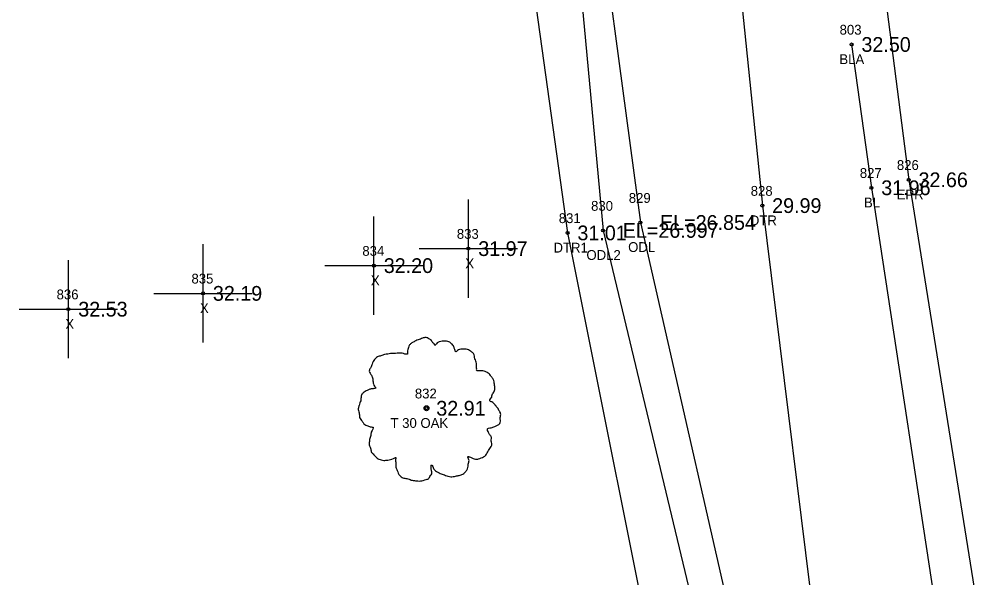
# Model space of a CAD drawing. Extents: x 2042211 to 2045853, y 303080 to 309569.
# Drawn here: x 2042754.4 to 2042852.8, y 307040.8 to 307097.7 of the extents above; entities that cross this region are included whole.
import ezdxf

# ---------------------------------------------------------------- set-up
doc = ezdxf.new("R2010")
doc.units = 0
for name, color, linetype in [('BR_500YR_SCOUR', 7, 'Continuous'), ('RD_DTM_BkLn1', 7, 'Continuous'), ('RD_DTM_BkLn_txCode', 7, 'Continuous'), ('RD_EX_H2O', 7, 'Continuous'), ('RD_EX_H2O_txCode', 7, 'Continuous'), ('RD_EX_Misc', 7, 'Continuous'), ('RD_EX_Misc_txCode', 7, 'Continuous'), ('RD_EX_Road', 7, 'Continuous'), ('RD_EX_Road_txCode', 7, 'Continuous'), ('RD_EX_TX_H2O_ELEV', 7, 'Continuous'), ('RD_EX_TX_Misc_ELEV', 7, 'Continuous'), ('RD_EX_TX_Road_ELEV', 7, 'Continuous'), ('RD_EX_TX_VEG_ELEV', 7, 'Continuous'), ('RD_EX_VEG_txCode', 7, 'Continuous'), ('RD_SMD_Locator', 7, 'Continuous')]:
    doc.layers.add(name, color=color, linetype=linetype)

msp = doc.modelspace()

# ---------------------------------------------------------------- linework, layer by layer
at = {"layer": 'BR_500YR_SCOUR'}
for centre, radius in [((2042795.884, 307058.081), 0.25), ((2042795.884, 307058.081), 0.15), ((2042795.871, 307058.062), 0.0001)]:
    msp.add_circle(centre, radius, dxfattribs=at)
for points in [[(2042796.016, 307065.248), (2042795.716, 307065.273), (2042795.391, 307065.173), (2042795.141, 307065.073), (2042794.916, 307064.998), (2042794.692, 307064.898), (2042794.392, 307064.723), (2042794.167, 307064.523), (2042794.042, 307064.273), (2042793.992, 307064.048), (2042793.942, 307063.774), (2042793.942, 307063.599), (2042793.817, 307063.574), (2042793.667, 307063.599), (2042793.417, 307063.674), (2042793.167, 307063.674), (2042792.917, 307063.674), (2042792.567, 307063.649), (2042792.218, 307063.649), (2042791.943, 307063.599), (2042791.618, 307063.549), (2042791.243, 307063.424), (2042790.893, 307063.299), (2042790.593, 307063.049), (2042790.343, 307062.574), (2042790.218, 307062.224), (2042790.069, 307061.974), (2042790.218, 307061.525), (2042790.393, 307061.175), (2042790.418, 307060.975), (2042790.493, 307060.55), (2042790.593, 307060.325), (2042790.718, 307060.125), (2042790.643, 307060.1), (2042790.268, 307060.05), (2042789.969, 307059.95), (2042789.544, 307059.725), (2042789.319, 307059.5), (2042789.219, 307059.175), (2042789.194, 307058.826), (2042789.094, 307058.626), (2042789.019, 307058.351), (2042788.994, 307058.276), (2042788.944, 307057.951), (2042789.044, 307057.501), (2042789.069, 307057.151), (2042789.194, 307056.926), (2042789.344, 307056.752), (2042789.519, 307056.502), (2042789.919, 307056.277), (2042790.243, 307056.177), (2042790.443, 307056.152), (2042790.268, 307055.652), (2042790.218, 307055.302), (2042790.094, 307054.902), (2042790.094, 307054.827), (2042790.044, 307054.353), (2042790.193, 307054.028), (2042790.268, 307053.653), (2042790.443, 307053.428), (2042790.718, 307053.128), (2042791.043, 307052.903), (2042791.543, 307052.778), (2042791.943, 307052.803), (2042792.518, 307052.978), (2042792.767, 307053.053), (2042792.742, 307052.878), (2042792.767, 307052.503), (2042792.767, 307052.079), (2042792.917, 307051.754), (2042793.017, 307051.479), (2042793.167, 307051.229), (2042793.492, 307051.004), (2042793.892, 307050.929), (2042794.317, 307050.779), (2042794.767, 307050.704), (2042795.266, 307050.679), (2042795.866, 307050.829), (2042796.141, 307050.954), (2042796.241, 307051.129), (2042796.441, 307051.504), (2042796.391, 307051.729), (2042796.416, 307052.329), (2042796.516, 307052.154), (2042796.691, 307051.804), (2042797.19, 307051.504), (2042797.59, 307051.329), (2042798.065, 307051.179), (2042798.365, 307051.104), (2042798.84, 307051.179), (2042799.215, 307051.254), (2042799.589, 307051.379), (2042799.889, 307051.654), (2042800.064, 307051.929), (2042800.114, 307052.204), (2042800.189, 307052.578), (2042800.239, 307052.753)], [(2042800.239, 307052.753), (2042800.164, 307052.928), (2042800.114, 307053.178), (2042800.189, 307053.153), (2042800.364, 307053.103), (2042800.639, 307052.978), (2042800.864, 307052.903), (2042801.189, 307052.928), (2042801.464, 307053.028), (2042801.913, 307053.303), (2042802.188, 307053.778), (2042802.463, 307054.178), (2042802.538, 307054.503), (2042802.488, 307054.727), (2042802.463, 307055.227), (2042802.263, 307055.477), (2042802.213, 307055.602), (2042802.113, 307056.002), (2042802.188, 307056.052), (2042802.463, 307056.102), (2042802.838, 307056.227), (2042803.113, 307056.352), (2042803.338, 307056.527), (2042803.413, 307056.752), (2042803.388, 307057.151), (2042803.438, 307057.551), (2042803.363, 307057.701), (2042803.263, 307057.851), (2042803.188, 307058.051), (2042803.038, 307058.201), (2042802.938, 307058.351), (2042802.838, 307058.451), (2042802.713, 307058.601), (2042802.538, 307058.726), (2042802.388, 307058.776), (2042802.338, 307058.926), (2042802.488, 307059.126), (2042802.538, 307059.225), (2042802.563, 307059.45), (2042802.788, 307059.8), (2042802.838, 307060.2), (2042802.788, 307060.625), (2042802.738, 307060.9), (2042802.588, 307061.175), (2042802.388, 307061.425), (2042802.263, 307061.599), (2042802.088, 307061.724), (2042801.763, 307061.849), (2042801.514, 307061.899), (2042801.164, 307061.899), (2042800.964, 307061.949), (2042800.989, 307061.999), (2042800.989, 307062.149), (2042800.989, 307062.424), (2042800.914, 307062.874), (2042800.764, 307063.374), (2042800.764, 307063.399), (2042800.664, 307063.649), (2042800.439, 307063.848), (2042800.264, 307063.948), (2042800.064, 307064.073), (2042799.814, 307064.098), (2042799.514, 307064.098), (2042799.24, 307064.048), (2042799.04, 307063.948), (2042798.865, 307063.823), (2042798.79, 307063.973), (2042798.69, 307064.273), (2042798.64, 307064.423), (2042798.49, 307064.598), (2042798.265, 307064.798), (2042797.815, 307064.923), (2042797.19, 307064.848), (2042796.891, 307064.648), (2042796.741, 307064.473), (2042796.691, 307064.598), (2042796.491, 307064.798), (2042796.391, 307064.973), (2042796.216, 307065.098), (2042796.066, 307065.198), (2042795.966, 307065.248)]]:
    msp.add_spline(points, degree=3, dxfattribs=at)
at = {"layer": 'RD_DTM_BkLn1'}
msp.add_lwpolyline([(2042839.169, 307095.106), (2042841.186, 307080.523), (2042848.71, 307031.328), (2042857.636, 306982.339), (2042868.252, 306933.785), (2042879.621, 306884.9), (2042891.371, 306836.606), (2042906.047, 306788.555), (2042920.383, 306740.357), (2042936.302, 306692.681), (2042942.201, 306670.77), (2042952.719, 306646.491), (2042972.882, 306600.437), (2042993.942, 306554.963), (2043015.194, 306509.481), (2043037.058, 306464.501), (2043060.221, 306420.453)], dxfattribs=at)
at = {"layer": 'RD_EX_H2O'}
for points in [[(2042809.741, 307126.164), (2042806.558, 307122.634), (2042790.31, 307116.781), (2042788.489, 307114.776), (2042791.888, 307113.566), (2042804.809, 307114.936), (2042810.254, 307075.927), (2042820.25, 307025.916), (2042830.402, 306977.214), (2042843.286, 306928.12), (2042852.907, 306878.242), (2042864.554, 306828.434), (2042879.232, 306781.717), (2042889.452, 306748.733), (2042886.162, 306741.984), (2042888.342, 306727.944), (2042896.131, 306676.354), (2042885.674, 306665.433), (2042857.251, 306612.72)], [(2042809.741, 307126.164), (2042815.006, 307124.307), (2042821.793, 307118.991), (2042825.803, 307110.204), (2042827.879, 307100.209), (2042830.079, 307078.706), (2042836.245, 307029.115), (2042845.477, 306980.043), (2042852.07, 306929.459), (2042864.584, 306881.255), (2042879.311, 306833.064), (2042893.367, 306784.782), (2042908.764, 306736.234), (2042928.775, 306689.39), (2042938.935, 306669.11)], [(2042812.202, 307117.747), (2042817.664, 307076.987), (2042828.965, 307027.386), (2042840.42, 306978.95), (2042848.435, 306929.659), (2042859.837, 306880.358), (2042873.681, 306831.671), (2042888.543, 306783.43), (2042900.594, 306749.272), (2042902.903, 306733.666), (2042926.042, 306688.214), (2042936.455, 306668.372), (2042947.444, 306643.989), (2042966.182, 306597.912), (2042985.34, 306551.144), (2042987.611, 306538.586)], [(2042810.023, 307117.36), (2042813.866, 307076.179), (2042825.646, 307027.003), (2042835.988, 306978.447), (2042846.189, 306929.265), (2042857.498, 306879.973), (2042870.301, 306830.673), (2042885.373, 306782.676), (2042895.573, 306748.275), (2042892.025, 306740.631), (2042891.661, 306731.268), (2042905.953, 306680.583), (2042906.869, 306643.176), (2042864.966, 306605.633)]]:
    msp.add_lwpolyline(points, dxfattribs=at)
at = {"layer": 'RD_EX_Misc'}
for p, q in [((2042800.156, 307069.328), (2042800.156, 307079.328)), ((2042790.538, 307067.597), (2042790.538, 307077.597)), ((2042773.139, 307064.774), (2042773.139, 307074.774)), ((2042795.156, 307074.328), (2042805.156, 307074.328)), ((2042759.432, 307063.165), (2042759.432, 307073.165)), ((2042785.538, 307072.597), (2042795.538, 307072.597)), ((2042768.139, 307069.774), (2042778.139, 307069.774)), ((2042754.432, 307068.165), (2042764.432, 307068.165))]:
    msp.add_line(p, q, dxfattribs=at)
at = {"layer": 'RD_EX_Road'}
msp.add_lwpolyline([(2042826.878, 307329.287), (2042828.013, 307279.816), (2042830.497, 307230.241), (2042834.094, 307180.367), (2042835.887, 307157.733), (2042833.55, 307154.384), (2042836.54, 307132.831), (2042837.327, 307130.114), (2042837.641, 307128.77), (2042839.219, 307126.163), (2042844.982, 307081.334), (2042852.857, 307032.13), (2042861.739, 306982.988), (2042871.664, 306934.616), (2042883.382, 306885.882), (2042895.938, 306837.564), (2042909.761, 306789.886)], dxfattribs=at)
at = {"layer": 'RD_SMD_Locator'}
for centre in [(2042839.169, 307095.106), (2042844.982, 307081.334), (2042841.186, 307080.523), (2042830.079, 307078.706), (2042817.664, 307076.987), (2042813.866, 307076.179), (2042810.254, 307075.927), (2042800.156, 307074.328), (2042790.538, 307072.597), (2042773.139, 307069.774), (2042759.432, 307068.165)]:
    msp.add_circle(centre, 0.15, dxfattribs=at)

# ---------------------------------------------------------------- texts
at = {"layer": 'RD_DTM_BkLn_txCode'}
for s, p in [('803', (2042837.948, 307096.106)), ('BLA', (2042837.925, 307093.106)), ('827', (2042840.005, 307081.523)), ('BL', (2042840.43, 307078.523))]:
    msp.add_text(s, height=1, dxfattribs=at).set_placement(p)
at = {"layer": 'RD_EX_H2O_txCode'}
for s, p in [('828', (2042828.897, 307079.706)), ('830', (2042812.645, 307078.179)), ('829', (2042816.483, 307078.987)), ('831', (2042809.357, 307076.927)), ('DTR', (2042828.811, 307076.706)), ('DTR1', (2042808.821, 307073.927)), ('ODL2', (2042812.173, 307073.179)), ('ODL', (2042816.42, 307073.987))]:
    msp.add_text(s, height=1, dxfattribs=at).set_placement(p)
at = {"layer": 'RD_EX_Misc_txCode'}
for s, p in [('833', (2042798.975, 307075.328)), ('834', (2042789.357, 307073.597)), ('X', (2042799.841, 307072.328)), ('835', (2042771.958, 307070.774)), ('X', (2042790.223, 307070.597)), ('836', (2042758.228, 307069.165)), ('X', (2042772.824, 307067.774)), ('X', (2042759.117, 307066.165))]:
    msp.add_text(s, height=1, dxfattribs=at).set_placement(p)
at = {"layer": 'RD_EX_Road_txCode'}
for s, p in [('826', (2042843.778, 307082.334)), ('EPR', (2042843.754, 307079.334))]:
    msp.add_text(s, height=1, dxfattribs=at).set_placement(p)
at = {"layer": 'RD_EX_TX_H2O_ELEV'}
for s, p in [('29.99', (2042831.079, 307077.956)), ('EL=26.854', (2042819.664, 307076.237)), ('31.01', (2042811.254, 307075.177)), ('EL=26.997', (2042815.866, 307075.429))]:
    msp.add_text(s, height=1.5, dxfattribs=at).set_placement(p)
at = {"layer": 'RD_EX_TX_Misc_ELEV'}
for s, p in [('32.50', (2042840.169, 307094.356)), ('31.96', (2042842.186, 307079.773)), ('31.97', (2042801.156, 307073.578)), ('32.20', (2042791.538, 307071.847)), ('32.19', (2042774.139, 307069.024)), ('32.53', (2042760.432, 307067.415))]:
    msp.add_text(s, height=1.5, dxfattribs=at).set_placement(p)
at = {"layer": 'RD_EX_TX_Road_ELEV'}
msp.add_text('32.66', height=1.5, dxfattribs=at).set_placement((2042845.982, 307080.584))
at = {"layer": 'RD_EX_TX_VEG_ELEV'}
msp.add_text('32.91', height=1.5, dxfattribs=at).set_placement((2042796.884, 307057.331))
at = {"layer": 'RD_EX_VEG_txCode'}
for s, p in [('832', (2042794.703, 307059.081)), ('T 30 OAK', (2042792.223, 307056.081))]:
    msp.add_text(s, height=1, dxfattribs=at).set_placement(p)

doc.saveas('drawing.dxf')
